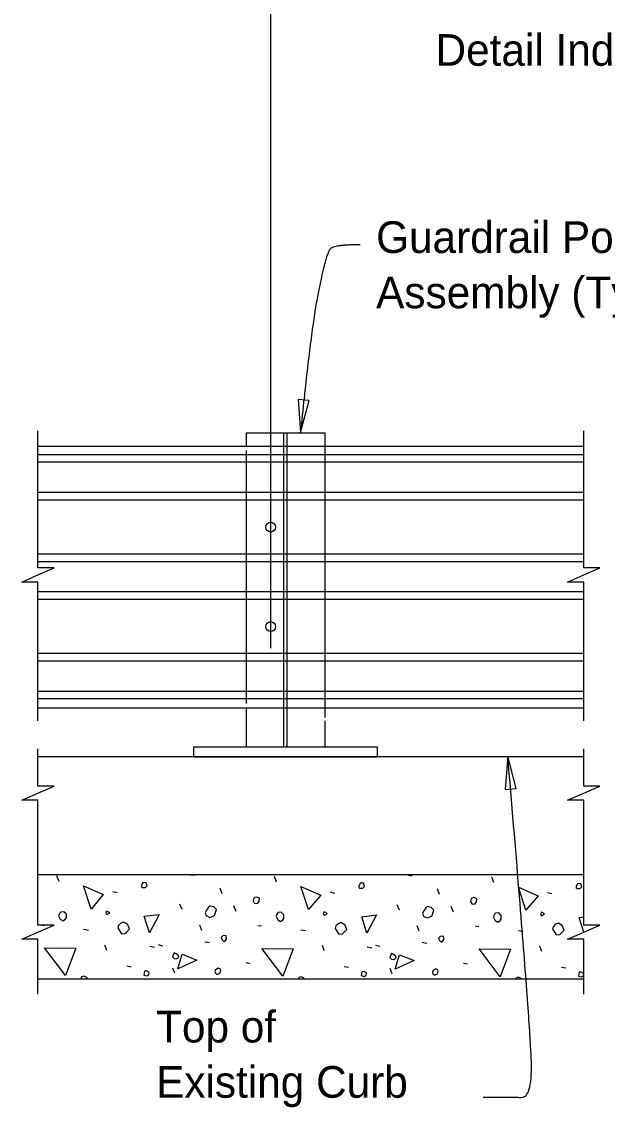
# Model space of a CAD drawing. Extents: x 21516.9 to 21586.2, y 56155.7 to 56195.
# Drawn here: x 21520.39 to 21524.12, y 56169.78 to 56176.69 of the extents above; entities that cross this region are included whole.
import ezdxf

# ---------------------------------------------------------------- set-up
doc = ezdxf.new("R2010")
doc.units = 0
for name, color, linetype in [('AdhocPoint_dp', 7, 'Continuous'), ('Border', 7, 'Continuous'), ('Patterning', 7, 'Continuous'), ('PlotBorder_dp', 7, 'Continuous'), ('TextMisc', 7, 'Continuous')]:
    doc.layers.add(name, color=color, linetype=linetype)

msp = doc.modelspace()

# ---------------------------------------------------------------- linework, layer by layer
at = {"layer": 'AdhocPoint_dp'}
for p, q in [((21523.9717, 56172.0121), (21520.4949, 56172.0121)), ((21520.4949, 56171.2621), (21523.9717, 56171.2621)), ((21523.9717, 56170.5954), (21520.4949, 56170.5954))]:
    msp.add_line(p, q, dxfattribs=at)
at = {"layer": 'Border'}
for p, q in [((21520.6304, 56171.2172), (21520.6163, 56171.2525)), ((21522.0151, 56171.2136), (21522.0009, 56171.249)), ((21523.3998, 56171.2101), (21523.3856, 56171.2455)), ((21520.971, 56171.1547), (21520.9992, 56171.1476)), ((21521.6692, 56171.1388), (21521.6551, 56171.1741)), ((21522.3556, 56171.1511), (21522.3839, 56171.1441)), ((21523.0539, 56171.1352), (21523.0398, 56171.1706)), ((21523.7403, 56171.1476), (21523.7686, 56171.1405)), ((21521.4129, 56171.038), (21521.3987, 56171.0734)), ((21522.7976, 56171.0345), (21522.7834, 56171.0698)), ((21521.757, 56171.0263), (21521.7428, 56171.0616)), ((21523.1417, 56171.0227), (21523.1275, 56171.0581)), ((21520.5102, 56170.9414), (21520.5349, 56170.9379)), ((21521.5384, 56170.9054), (21521.526, 56170.939)), ((21521.8949, 56170.9379), (21521.9196, 56170.9343)), ((21522.9231, 56170.9019), (21522.9107, 56170.9355)), ((21523.2795, 56170.9343), (21523.3043, 56170.9308)), ((21520.786, 56170.9131), (21520.816, 56170.9078)), ((21522.1706, 56170.9096), (21522.2007, 56170.9043)), ((21523.5553, 56170.9061), (21523.5854, 56170.9007)), ((21520.9345, 56170.7788), (21520.9221, 56170.8124)), ((21521.2085, 56170.8053), (21521.2367, 56170.7982)), ((21521.2609, 56170.8153), (21521.2891, 56170.8082)), ((21521.5572, 56170.8336), (21521.5873, 56170.8283)), ((21522.3191, 56170.7752), (21522.3068, 56170.8088)), ((21522.5931, 56170.8018), (21522.6214, 56170.7947)), ((21522.6455, 56170.8117), (21522.6738, 56170.8047)), ((21522.9419, 56170.83), (21522.972, 56170.8247)), ((21523.7038, 56170.7717), (21523.6914, 56170.8053)), ((21521.0617, 56170.6798), (21521.0882, 56170.6745)), ((21521.3669, 56170.6327), (21521.3546, 56170.6663)), ((21521.8206, 56170.701), (21521.8471, 56170.6957)), ((21522.4464, 56170.6762), (21522.4729, 56170.6709)), ((21522.7516, 56170.6291), (21522.7392, 56170.6627)), ((21523.2053, 56170.6975), (21523.2318, 56170.6922)), ((21523.8311, 56170.6727), (21523.8576, 56170.6674))]:
    msp.add_line(p, q, dxfattribs=at)
for points in [[(21521.1583, 56171.1794), (21521.1795, 56171.1794), (21521.1902, 56171.19), (21521.1849, 56171.2095), (21521.1619, 56171.2112), (21521.1583, 56171.2006), (21521.153, 56171.1918), (21521.1583, 56171.1794), (21521.1548, 56171.183)], [(21521.4687, 56171.2621), (21521.4695, 56171.2607), (21521.4907, 56171.2572), (21521.4934, 56171.2621)], [(21522.543, 56171.1759), (21522.5642, 56171.1759), (21522.5748, 56171.1865), (21522.5695, 56171.2059), (21522.5465, 56171.2077), (21522.543, 56171.1971), (21522.5377, 56171.1883), (21522.543, 56171.1759), (21522.5395, 56171.1794)], [(21522.8514, 56171.2621), (21522.8541, 56171.2572), (21522.8754, 56171.2537), (21522.88, 56171.2621)], [(21523.9277, 56171.1724), (21523.9489, 56171.1724), (21523.9595, 56171.183), (21523.9542, 56171.2024), (21523.9312, 56171.2042), (21523.9277, 56171.1936), (21523.9224, 56171.1847), (21523.9277, 56171.1724), (21523.9242, 56171.1759)], [(21520.8337, 56171.0422), (21520.786, 56171.1889), (21520.9115, 56171.1341), (21520.8337, 56171.0422)], [(21522.2184, 56171.0386), (21522.1706, 56171.1854), (21522.2961, 56171.1306), (21522.2184, 56171.0386)], [(21523.603, 56171.0351), (21523.5553, 56171.1818), (21523.6808, 56171.127), (21523.603, 56171.0351)], [(21521.8666, 56171.0934), (21521.8754, 56171.0775), (21521.8949, 56171.0793), (21521.9037, 56171.0917), (21521.9055, 56171.1111), (21521.8931, 56171.1164), (21521.8843, 56171.1182), (21521.8737, 56171.1146), (21521.8701, 56171.1111), (21521.8666, 56171.0934)], [(21523.2513, 56171.0899), (21523.2601, 56171.074), (21523.2795, 56171.0758), (21523.2884, 56171.0881), (21523.2902, 56171.1076), (21523.2778, 56171.1129), (21523.2689, 56171.1146), (21523.2583, 56171.1111), (21523.2548, 56171.1076), (21523.2513, 56171.0899)], [(21520.6269, 56170.998), (21520.6375, 56170.9768), (21520.6551, 56170.9662), (21520.6693, 56170.9768), (21520.6764, 56170.9874), (21520.6764, 56171.0086), (21520.6604, 56171.0245), (21520.641, 56171.0227), (21520.6322, 56171.0139), (21520.6269, 56170.998)], [(21520.9327, 56171.0068), (21520.9521, 56171.0157), (21520.9451, 56171.0227), (21520.9327, 56171.028), (21520.9274, 56171.0157), (21520.9327, 56171.0068)], [(21521.2061, 56170.8913), (21521.1725, 56170.9956), (21521.2662, 56171.008), (21521.2061, 56170.8913)], [(21521.5667, 56171.0009), (21521.5897, 56170.9885), (21521.6197, 56171.0009), (21521.6321, 56171.038), (21521.6144, 56171.0557), (21521.5914, 56171.061), (21521.5808, 56171.0539), (21521.5685, 56171.0345), (21521.5596, 56171.0186), (21521.5667, 56171.0009)], [(21522.0115, 56170.9944), (21522.0221, 56170.9732), (21522.0398, 56170.9626), (21522.054, 56170.9732), (21522.061, 56170.9838), (21522.061, 56171.005), (21522.0451, 56171.021), (21522.0257, 56171.0192), (21522.0168, 56171.0103), (21522.0115, 56170.9944)], [(21522.3174, 56171.0033), (21522.3368, 56171.0121), (21522.3297, 56171.0192), (21522.3174, 56171.0245), (21522.3121, 56171.0121), (21522.3174, 56171.0033)], [(21522.5907, 56170.8877), (21522.5572, 56170.992), (21522.6508, 56171.0044), (21522.5907, 56170.8877)], [(21522.9514, 56170.9973), (21522.9743, 56170.985), (21523.0044, 56170.9973), (21523.0168, 56171.0345), (21522.9991, 56171.0521), (21522.9761, 56171.0575), (21522.9655, 56171.0504), (21522.9531, 56171.0309), (21522.9443, 56171.015), (21522.9514, 56170.9973)], [(21523.3962, 56170.9909), (21523.4068, 56170.9697), (21523.4245, 56170.9591), (21523.4386, 56170.9697), (21523.4457, 56170.9803), (21523.4457, 56171.0015), (21523.4298, 56171.0174), (21523.4104, 56171.0157), (21523.4015, 56171.0068), (21523.3962, 56170.9909)], [(21523.702, 56170.9997), (21523.7215, 56171.0086), (21523.7144, 56171.0157), (21523.702, 56171.021), (21523.6967, 56171.0086), (21523.702, 56170.9997)], [(21521.0034, 56170.922), (21521.0264, 56170.8848), (21521.0494, 56170.8866), (21521.0582, 56170.8954), (21521.0776, 56170.9149), (21521.0653, 56170.9449), (21521.0405, 56170.9591), (21521.0228, 56170.952), (21521.0087, 56170.9379), (21521.0034, 56170.922)], [(21522.3881, 56170.9184), (21522.4111, 56170.8813), (21522.434, 56170.8831), (21522.4429, 56170.8919), (21522.4623, 56170.9114), (21522.4499, 56170.9414), (21522.4252, 56170.9555), (21522.4075, 56170.9485), (21522.3934, 56170.9343), (21522.3881, 56170.9184)], [(21523.7728, 56170.9149), (21523.7957, 56170.8778), (21523.8187, 56170.8795), (21523.8276, 56170.8884), (21523.847, 56170.9078), (21523.8346, 56170.9379), (21523.8099, 56170.952), (21523.7922, 56170.9449), (21523.7781, 56170.9308), (21523.7728, 56170.9149)], [(21523.9717, 56170.8957), (21523.9418, 56170.9885), (21523.9717, 56170.9925)], [(21521.6686, 56170.8459), (21521.6792, 56170.8353), (21521.6898, 56170.8424), (21521.6969, 56170.853), (21521.6933, 56170.8707), (21521.6845, 56170.8725), (21521.6721, 56170.8707), (21521.6615, 56170.8601), (21521.6686, 56170.8459)], [(21523.0533, 56170.8424), (21523.0639, 56170.8318), (21523.0745, 56170.8389), (21523.0816, 56170.8495), (21523.078, 56170.8672), (21523.0692, 56170.8689), (21523.0568, 56170.8672), (21523.0462, 56170.8566), (21523.0533, 56170.8424)], [(21520.6711, 56170.6179), (21520.5367, 56170.7947), (21520.7365, 56170.7929), (21520.6711, 56170.6179)], [(21522.0557, 56170.6144), (21521.9214, 56170.7911), (21522.1211, 56170.7894), (21522.0557, 56170.6144)], [(21521.3634, 56170.7269), (21521.3758, 56170.7251), (21521.3881, 56170.7304), (21521.3917, 56170.741), (21521.3864, 56170.7499), (21521.3758, 56170.7569), (21521.3634, 56170.7622), (21521.3563, 56170.7481), (21521.3528, 56170.7375), (21521.3634, 56170.7269)], [(21521.3857, 56170.6621), (21521.414, 56170.754), (21521.5077, 56170.7169), (21521.3857, 56170.6621)], [(21522.7481, 56170.7233), (21522.7604, 56170.7216), (21522.7728, 56170.7269), (21522.7764, 56170.7375), (21522.7711, 56170.7463), (21522.7604, 56170.7534), (21522.7481, 56170.7587), (21522.741, 56170.7446), (21522.7375, 56170.734), (21522.7481, 56170.7233)], [(21522.7704, 56170.6586), (21522.7987, 56170.7505), (21522.8924, 56170.7134), (21522.7704, 56170.6586)], [(21523.4404, 56170.6108), (21523.3061, 56170.7876), (21523.5058, 56170.7858), (21523.4404, 56170.6108)], [(21521.6332, 56170.6267), (21521.6403, 56170.6267), (21521.6545, 56170.6338), (21521.6598, 56170.6497), (21521.658, 56170.6586), (21521.6438, 56170.6656), (21521.6262, 56170.655), (21521.6226, 56170.6444), (21521.6262, 56170.6338), (21521.6332, 56170.6267)], [(21523.0179, 56170.6232), (21523.025, 56170.6232), (21523.0391, 56170.6303), (21523.0444, 56170.6462), (21523.0427, 56170.655), (21523.0285, 56170.6621), (21523.0108, 56170.6515), (21523.0073, 56170.6409), (21523.0108, 56170.6303), (21523.0179, 56170.6232)], [(21520.8122, 56170.5954), (21520.8125, 56170.5967), (21520.8036, 56170.6055), (21520.7877, 56170.6144), (21520.7718, 56170.6091), (21520.7673, 56170.5954)], [(21521.1696, 56170.6214), (21521.189, 56170.6161), (21521.2014, 56170.625), (21521.2032, 56170.6373), (21521.1996, 56170.6409), (21521.1855, 56170.648), (21521.1731, 56170.6462), (21521.1713, 56170.6338), (21521.1696, 56170.6214)], [(21522.1949, 56170.5954), (21522.1883, 56170.602), (21522.1724, 56170.6108), (21522.1565, 56170.6055), (21522.1531, 56170.5954)], [(21522.5542, 56170.6179), (21522.5737, 56170.6126), (21522.5861, 56170.6214), (21522.5878, 56170.6338), (21522.5843, 56170.6373), (21522.5702, 56170.6444), (21522.5578, 56170.6427), (21522.556, 56170.6303), (21522.5542, 56170.6179)], [(21523.576, 56170.5954), (21523.573, 56170.5985), (21523.5571, 56170.6073), (21523.5412, 56170.602), (21523.539, 56170.5954)], [(21523.9717, 56170.6311), (21523.969, 56170.6338), (21523.9548, 56170.6409), (21523.9425, 56170.6391), (21523.9407, 56170.6267), (21523.9389, 56170.6144)], [(21523.9389, 56170.6144), (21523.9584, 56170.6091), (21523.9707, 56170.6179), (21523.9717, 56170.6248)]]:
    msp.add_lwpolyline(points, dxfattribs=at)
at = {"layer": 'Patterning'}
for p, q in [((21522.0612, 56172.0747), (21522.0612, 56174.0747)), ((21522.0821, 56172.0747), (21522.0821, 56174.0747)), ((21522.3216, 56174.0747), (21522.3216, 56172.2617)), ((21521.8216, 56173.9628), (21521.8216, 56172.3509))]:
    msp.add_line(p, q, dxfattribs=at)
at = {"layer": 'PlotBorder_dp'}
msp.add_line((21521.9779, 56172.7046), (21521.9779, 56186.7114), dxfattribs=at)
for points in [[(21522.1675, 56174.0766), (21522.2232, 56174.2803), (21522.153, 56174.2873)], [(21523.4884, 56172.0149), (21523.4708, 56171.8044), (21523.5411, 56171.8104)]]:
    msp.add_lwpolyline(points, close=True, dxfattribs=at)
for points in [[(21520.4949, 56172.2416), (21520.4949, 56173.1248), (21520.3916, 56173.1248), (21520.4949, 56173.1698), (21520.5982, 56173.2148), (21520.4949, 56173.2148), (21520.4949, 56174.0878)], [(21523.9717, 56172.2416), (21523.9717, 56173.1248), (21523.8684, 56173.1248), (21523.9717, 56173.1698), (21524.0751, 56173.2148), (21523.9717, 56173.2148), (21523.9717, 56174.0878)], [(21520.4949, 56171.2647), (21520.4949, 56171.7348), (21520.3916, 56171.7348), (21520.4949, 56171.7798), (21520.5982, 56171.8248), (21520.4949, 56171.8248), (21520.4949, 56172.0622)], [(21523.9717, 56171.2647), (21523.9717, 56171.7348), (21523.8684, 56171.7348), (21523.9717, 56171.7798), (21524.0751, 56171.8248), (21523.9717, 56171.8248), (21523.9717, 56172.0622)], [(21520.4949, 56170.4996), (21520.4949, 56170.8503), (21520.3916, 56170.8503), (21520.4949, 56170.8953), (21520.5982, 56170.9403), (21520.4949, 56170.9403), (21520.4949, 56171.2647)], [(21523.9717, 56170.4996), (21523.9717, 56170.8503), (21523.8684, 56170.8503), (21523.9717, 56170.8953), (21524.0751, 56170.9403), (21523.9717, 56170.9403), (21523.9717, 56171.2647)]]:
    msp.add_lwpolyline(points, dxfattribs=at)
for points in [[(21522.5468, 56175.273), (21522.3833, 56175.273), (21522.3309, 56175.2207), (21522.2328, 56174.7333), (21522.1675, 56174.0765)], [(21523.3315, 56169.8428), (21523.5146, 56169.8428), (21523.6388, 56169.8428), (21523.6388, 56170.2353), (21523.4884, 56172.0149)]]:
    msp.add_open_spline(points, degree=2, dxfattribs=at)
at = {"layer": 'TextMisc'}
for p, q in [((21521.8216, 56174.0747), (21522.3216, 56174.0747)), ((21521.8216, 56174.0747), (21521.8216, 56173.9913)), ((21520.4949, 56173.9913), (21523.9717, 56173.9913)), ((21523.9717, 56173.9357), (21520.4949, 56173.9357)), ((21523.9717, 56173.8875), (21520.4949, 56173.8875)), ((21523.9717, 56173.6947), (21520.4949, 56173.6947)), ((21523.9717, 56173.6465), (21520.4949, 56173.6465)), ((21523.9717, 56173.3025), (21520.4949, 56173.3025)), ((21523.9717, 56173.2543), (21520.4949, 56173.2543)), ((21523.9717, 56173.0615), (21520.4949, 56173.0615)), ((21523.9717, 56173.0133), (21520.4949, 56173.0133)), ((21523.9717, 56172.6694), (21520.4949, 56172.6694)), ((21523.9717, 56172.6212), (21520.4949, 56172.6212)), ((21523.9717, 56172.4283), (21520.4949, 56172.4283)), ((21523.9717, 56172.3801), (21520.4949, 56172.3801)), ((21520.4949, 56172.3246), (21523.9717, 56172.3246)), ((21521.8216, 56172.3247), (21521.8216, 56172.0747)), ((21522.3216, 56172.2413), (21522.3216, 56172.0747)), ((21521.4883, 56172.0747), (21522.655, 56172.0747)), ((21521.4883, 56172.0122), (21521.4883, 56172.0747)), ((21521.8216, 56172.0747), (21522.3216, 56172.0747)), ((21522.655, 56172.0747), (21522.655, 56172.0122)), ((21521.4883, 56172.0122), (21522.655, 56172.0122))]:
    msp.add_line(p, q, dxfattribs=at)
for centre in [(21521.9779, 56173.4746), (21521.9779, 56172.8414)]:
    msp.add_circle(centre, 0.0312, dxfattribs=at)

# ---------------------------------------------------------------- texts
at = {"layer": 'PlotBorder_dp'}
for s, p in [('Detail Index 460-470, Sheet 2 (Typ.)', (21523.0278, 56176.4132)), ('Guardrail Post ', (21522.6492, 56175.221)), ('Assembly (Typ.)', (21522.6492, 56174.869)), ('Top of ', (21521.2477, 56170.192)), ('Existing Curb', (21521.2477, 56169.84))]:
    msp.add_text(s, height=0.2016, dxfattribs=at).set_placement(p)

doc.saveas('drawing.dxf')
